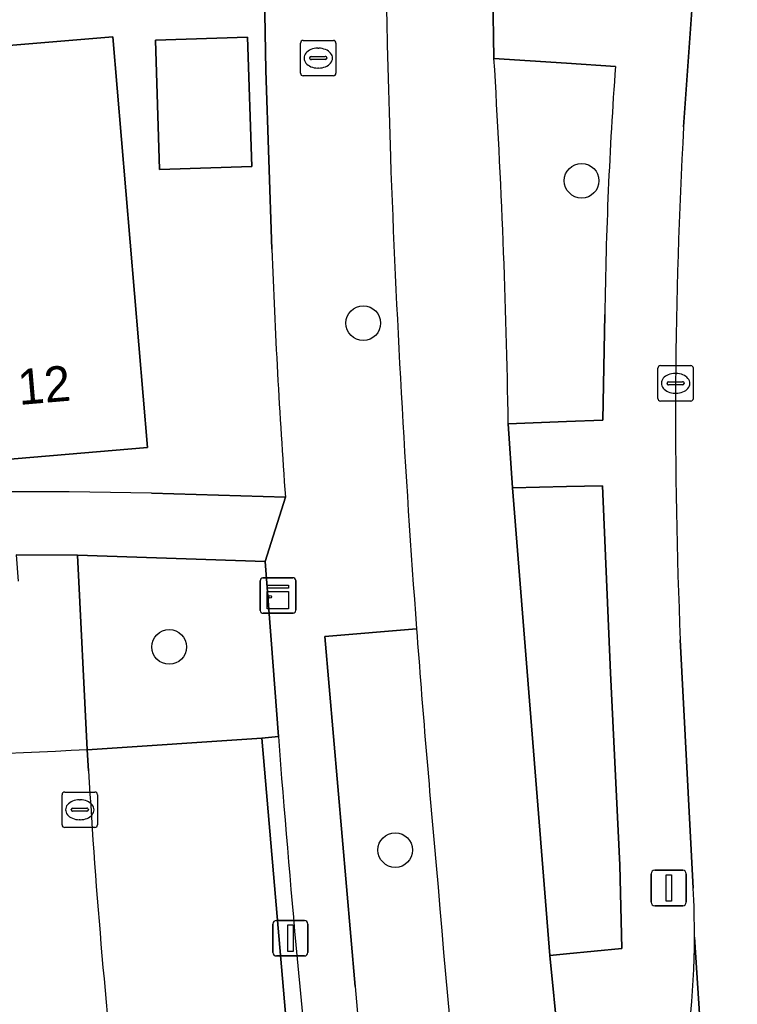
# Model space of a CAD drawing. Extents: x 160157 to 160921, y 381516 to 382045.
# Drawn here: x 160484.57 to 160504.82, y 381640.16 to 381667.92 of the extents above; entities that cross this region are included whole.
import ezdxf

# ---------------------------------------------------------------- set-up
doc = ezdxf.new("R2010")
doc.units = 0
for name, color, linetype in [('IMGEO_Berm_groen', 7, 'Continuous'), ('IMGEO_Boom', 7, 'Continuous'), ('IMGEO_Brandkraan', 7, 'Continuous'), ('IMGEO_Erf', 7, 'Continuous'), ('IMGEO_Fietspad_gesloten', 7, 'Continuous'), ('IMGEO_Groenvoorziening', 7, 'Continuous'), ('IMGEO_Kast', 7, 'Continuous'), ('IMGEO_Kolk', 7, 'Continuous'), ('IMGEO_Lichtmast', 7, 'Continuous'), ('IMGEO_Pand', 7, 'Continuous'), ('IMGEO_Pand_nummerreeks', 7, 'Continuous'), ('IMGEO_Parkeervlak_open', 7, 'Continuous'), ('IMGEO_Rijbaan_lokaal_open', 7, 'Continuous'), ('IMGEO_Rijbaan_regionaal_gesloten', 7, 'Continuous'), ('IMGEO_Verkeerseiland_open', 7, 'Continuous'), ('IMGEO_Voetpad_open', 7, 'Continuous')]:
    doc.layers.add(name, color=color, linetype=linetype)

msp = doc.modelspace()

# ---------------------------------------------------------------- linework, layer by layer
at = {"layer": 'IMGEO_Berm_groen'}
for points in [[(160501.377, 381666.605), (160500, 381666.695), (160497.95, 381666.828)], [(160498.353, 381656.527), (160500, 381656.592), (160501.02, 381656.633), (160501.077, 381659.61)]]:
    msp.add_lwpolyline(points, dxfattribs=at)
msp.add_lwpolyline([(160501.233, 381649.509), (160501.011, 381654.781), (160500, 381654.757), (160498.469, 381654.721), (160499.525, 381641.531), (160500, 381641.577), (160501.557, 381641.728), (160501.502, 381644.083)], close=True, dxfattribs=at)
for centre, radius, start, end in [((160263.469, 381652.496), 234.919, 0.98316, 3.49766), ((160618.795, 381658.065), 117.728, 175.84024, 179.24819)]:
    msp.add_arc(centre, radius, start, end, dxfattribs=at)
at = {"layer": 'IMGEO_Boom'}
for centre in [(160500.423, 381663.382), (160494.263, 381659.367), (160488.788, 381650.234), (160495.165, 381644.507)]:
    msp.add_circle(centre, 0.489, dxfattribs=at)
at = {"layer": 'IMGEO_Brandkraan'}
for p, q in [((160492.491, 381666.413), (160492.491, 381667.265)), ((160492.566, 381667.339), (160493.418, 381667.339)), ((160493.492, 381667.265), (160493.492, 381666.413)), ((160492.979, 381667.119), (160493.004, 381667.119)), ((160492.75, 381666.833), (160492.75, 381666.845)), ((160493.188, 381666.796), (160492.79, 381666.796)), ((160492.793, 381666.882), (160493.191, 381666.882)), ((160493.234, 381666.845), (160493.234, 381666.833)), ((160493.002, 381666.559), (160492.977, 381666.559)), ((160493.418, 381666.339), (160492.566, 381666.339))]:
    msp.add_line(p, q, dxfattribs=at)
for points in [[(160492.491, 381666.413), (160492.491, 381667.265)], [(160492.566, 381667.339), (160493.418, 381667.339)], [(160493.492, 381667.265), (160493.492, 381666.413)], [(160493.418, 381666.339), (160492.566, 381666.339)]]:
    msp.add_lwpolyline(points, dxfattribs=at)
for centre, radius, start, end in [((160492.568, 381667.263), 0.0765, 91.552, 178.448), ((160492.568, 381667.263), 0.0765, 91.552, 178.448), ((160493.416, 381667.263), 0.0765, 1.552, 88.448), ((160493.416, 381667.263), 0.0765, 1.552, 88.448), ((160492.79, 381666.842), 0.0403, 85.8775, 175.7526), ((160492.787, 381666.832), 0.0366, 178.938, 274.7102), ((160493.191, 381666.839), 0.043, 264.8664, 352.4533), ((160493.195, 381666.844), 0.0386, 1.7309, 96.639), ((160492.568, 381666.415), 0.0765, 181.552, 268.448), ((160492.568, 381666.415), 0.0765, 181.552, 268.448), ((160493.416, 381666.415), 0.0765, 271.552, 358.448), ((160493.416, 381666.415), 0.0765, 271.552, 358.448)]:
    msp.add_arc(centre, radius, start, end, dxfattribs=at)
for centre, major_axis, ratio, start_param, end_param in [((160492.978, 381666.839), (-0.387, 0.002), 0.722429, 4.712389, 7.853982), ((160493.003, 381666.839), (-0.39, 0.002), 0.717154, 1.570796, 4.712389)]:
    msp.add_ellipse(centre, major_axis=major_axis, ratio=ratio, start_param=start_param, end_param=end_param, dxfattribs=at)
at = {"layer": 'IMGEO_Erf'}
for points in [[(160491.686, 381661.452), (160491.512, 381666.491), (160491.457, 381669.708), (160491.439, 381672.439), (160491.376, 381681.789), (160491.463, 381687.593), (160491.694, 381694.13), (160492.728, 381711.927)], [(160488.29, 381654.567), (160492.066, 381654.457)]]:
    msp.add_lwpolyline(points, dxfattribs=at)
for points in [[(160461.315, 381665.237), (160466.815, 381665.701), (160466.916, 381664.505), (160471.988, 381664.933), (160472.089, 381663.737), (160476.737, 381664.143), (160476.65, 381665.329), (160481.757, 381665.774), (160481.655, 381666.978), (160487.192, 381667.435), (160488.176, 381655.861), (160482.64, 381655.389), (160477.518, 381654.953), (160472.87, 381654.556), (160467.799, 381654.124), (160462.295, 381653.655)], [(160488.396, 381667.341), (160490.999, 381667.427), (160491.118, 381663.781), (160488.516, 381663.696)]]:
    msp.add_lwpolyline(points, close=True, dxfattribs=at)
for centre, radius, start, end in [((160679.472, 381668.146), 187.905, 182.04142, 184.1776), ((160485.125, 381542.988), 111.624, 88.37544, 97.91678)]:
    msp.add_arc(centre, radius, start, end, dxfattribs=at)
at = {"layer": 'IMGEO_Fietspad_gesloten'}
for points in [[(160497.95, 381666.828), (160497.922, 381668.666)], [(160505.409, 381601.39), (160504.111, 381608.172), (160502.378, 381618.435), (160501.413, 381625.031), (160501.101, 381627.161), (160500, 381636.8), (160499.525, 381641.531), (160498.469, 381654.721), (160498.353, 381656.527)]]:
    msp.add_lwpolyline(points, dxfattribs=at)
for centre, radius, start, end in [((160961.225, 381678.785), 466.43, 179.32125, 181.81004), ((160263.469, 381652.496), 234.919, 0.98316, 3.49766), ((160848.429, 381676.959), 353.637, 182.09162, 184.25039), ((160844.842, 381676.565), 350.03, 184.22954, 185.32615), ((160833.391, 381670.807), 338.126, 184.53487, 187.87102)]:
    msp.add_arc(centre, radius, start, end, dxfattribs=at)
at = {"layer": 'IMGEO_Groenvoorziening'}
msp.add_lwpolyline([(160491.492, 381652.649), (160486.196, 381652.822), (160486.472, 381647.33), (160491.401, 381647.664), (160491.866, 381647.705), (160491.667, 381650.431)], close=True, dxfattribs=at)
for points in [[(160495.765, 381650.749), (160493.18, 381650.533), (160494.031, 381640.656)], [(160491.866, 381647.705), (160491.401, 381647.664), (160492.337, 381636.731), (160487.421, 381636.32), (160487.553, 381635.049), (160492.41, 381635.887)]]:
    msp.add_lwpolyline(points, dxfattribs=at)
for centre, radius, start, end in [((160844.842, 381676.565), 350.03, 184.22954, 185.32615), ((160879.416, 381677.449), 388.689, 184.38877, 188.09689), ((160833.391, 381670.807), 338.126, 184.53487, 187.87102), ((160792.557, 381665.833), 299.586, 184.82081, 190.09257)]:
    msp.add_arc(centre, radius, start, end, dxfattribs=at)
at = {"layer": 'IMGEO_Kast'}
for p, q in [((160491.357, 381651.26), (160491.357, 381652.101)), ((160491.357, 381652.101), (160491.357, 381651.26)), ((160491.432, 381652.185), (160492.273, 381652.185)), ((160492.273, 381652.185), (160491.432, 381652.185)), ((160492.357, 381652.11), (160492.357, 381651.269)), ((160492.357, 381651.269), (160492.357, 381652.11)), ((160492.282, 381651.185), (160491.441, 381651.185)), ((160491.441, 381651.185), (160492.282, 381651.185))]:
    msp.add_line(p, q, dxfattribs=at)
for points in [[(160491.552, 381651.975), (160492.152, 381651.975), (160492.152, 381651.89), (160491.552, 381651.89), (160491.552, 381651.975)], [(160491.552, 381651.8), (160492.152, 381651.8), (160492.152, 381651.311), (160491.552, 381651.311), (160491.552, 381651.8)]]:
    msp.add_lwpolyline(points, dxfattribs=at)
msp.add_circle((160491.636, 381651.649), 0.0377, dxfattribs=at)
for centre, start, end in [((160491.435, 381652.107), 92.4484, 184.2845), ((160491.435, 381652.107), 92.4484, 184.2845), ((160492.279, 381652.107), 2.4484, 94.2845), ((160492.279, 381652.107), 2.4484, 94.2845), ((160491.435, 381651.263), 182.4484, 274.2845), ((160491.435, 381651.263), 182.4484, 274.2845), ((160492.279, 381651.263), 272.4484, 4.2845), ((160492.279, 381651.263), 272.4484, 4.2845)]:
    msp.add_arc(centre, 0.0779, start, end, dxfattribs=at)
at = {"layer": 'IMGEO_Kolk'}
for p, q in [((160502.573, 381657.243), (160502.573, 381658.095)), ((160502.648, 381658.169), (160503.5, 381658.169)), ((160503.574, 381658.095), (160503.574, 381657.243)), ((160503.061, 381657.949), (160503.086, 381657.949)), ((160502.832, 381657.663), (160502.832, 381657.675)), ((160503.27, 381657.626), (160502.872, 381657.626)), ((160502.875, 381657.712), (160503.273, 381657.712)), ((160503.316, 381657.675), (160503.316, 381657.663)), ((160503.084, 381657.389), (160503.059, 381657.389)), ((160503.5, 381657.169), (160502.648, 381657.169)), ((160485.839, 381646.143), (160486.691, 381646.143)), ((160485.764, 381645.217), (160485.764, 381646.069)), ((160486.252, 381645.923), (160486.277, 381645.923)), ((160486.765, 381646.069), (160486.765, 381645.217)), ((160486.023, 381645.637), (160486.023, 381645.649)), ((160486.461, 381645.6), (160486.063, 381645.6)), ((160486.066, 381645.686), (160486.464, 381645.686)), ((160486.507, 381645.649), (160486.507, 381645.637)), ((160486.275, 381645.363), (160486.25, 381645.363)), ((160486.691, 381645.143), (160485.839, 381645.143))]:
    msp.add_line(p, q, dxfattribs=at)
for points in [[(160502.573, 381657.243), (160502.573, 381658.095)], [(160502.648, 381658.169), (160503.5, 381658.169)], [(160503.574, 381658.095), (160503.574, 381657.243)], [(160503.5, 381657.169), (160502.648, 381657.169)], [(160485.839, 381646.143), (160486.691, 381646.143)], [(160485.764, 381645.217), (160485.764, 381646.069)], [(160486.765, 381646.069), (160486.765, 381645.217)], [(160486.691, 381645.143), (160485.839, 381645.143)]]:
    msp.add_lwpolyline(points, dxfattribs=at)
for centre, radius, start, end in [((160502.65, 381658.093), 0.0765, 91.552, 178.448), ((160502.65, 381658.093), 0.0765, 91.552, 178.448), ((160503.498, 381658.093), 0.0765, 1.552, 88.448), ((160503.498, 381658.093), 0.0765, 1.552, 88.448), ((160502.872, 381657.672), 0.0403, 85.8775, 175.7526), ((160502.869, 381657.662), 0.0366, 178.938, 274.7102), ((160503.273, 381657.669), 0.043, 264.8664, 352.4533), ((160503.277, 381657.674), 0.0386, 1.7309, 96.639), ((160502.65, 381657.245), 0.0765, 181.552, 268.448), ((160502.65, 381657.245), 0.0765, 181.552, 268.448), ((160503.498, 381657.245), 0.0765, 271.552, 358.448), ((160503.498, 381657.245), 0.0765, 271.552, 358.448), ((160485.841, 381646.067), 0.0765, 91.552, 178.448), ((160485.841, 381646.067), 0.0765, 91.552, 178.448), ((160486.689, 381646.067), 0.0765, 1.552, 88.448), ((160486.689, 381646.067), 0.0765, 1.552, 88.448), ((160486.063, 381645.646), 0.0403, 85.8775, 175.7526), ((160486.06, 381645.636), 0.0366, 178.938, 274.7102), ((160486.464, 381645.643), 0.043, 264.8664, 352.4533), ((160486.468, 381645.648), 0.0386, 1.7309, 96.639), ((160485.841, 381645.219), 0.0765, 181.552, 268.448), ((160485.841, 381645.219), 0.0765, 181.552, 268.448), ((160486.689, 381645.219), 0.0765, 271.552, 358.448), ((160486.689, 381645.219), 0.0765, 271.552, 358.448)]:
    msp.add_arc(centre, radius, start, end, dxfattribs=at)
for centre, major_axis, ratio, start_param, end_param in [((160503.06, 381657.669), (-0.387, 0.002), 0.722429, 4.712389, 7.853982), ((160503.085, 381657.669), (-0.39, 0.002), 0.717154, 1.570796, 4.712389), ((160486.251, 381645.643), (-0.387, 0.002), 0.722429, 4.712389, 7.853982), ((160486.276, 381645.643), (-0.39, 0.002), 0.717154, 1.570796, 4.712389)]:
    msp.add_ellipse(centre, major_axis=major_axis, ratio=ratio, start_param=start_param, end_param=end_param, dxfattribs=at)
at = {"layer": 'IMGEO_Lichtmast'}
for p, q in [((160502.484, 381643.938), (160503.274, 381643.938)), ((160503.274, 381643.938), (160502.484, 381643.938)), ((160502.384, 381643.038), (160502.384, 381643.838)), ((160502.384, 381643.838), (160502.384, 381643.038)), ((160503.374, 381643.838), (160503.374, 381643.038)), ((160503.374, 381643.038), (160503.374, 381643.838)), ((160503.274, 381642.938), (160502.484, 381642.938)), ((160502.484, 381642.938), (160503.274, 381642.938)), ((160491.811, 381642.521), (160492.601, 381642.521)), ((160492.601, 381642.521), (160491.811, 381642.521)), ((160491.711, 381641.621), (160491.711, 381642.421)), ((160491.711, 381642.421), (160491.711, 381641.621)), ((160492.701, 381642.421), (160492.701, 381641.621)), ((160492.701, 381641.621), (160492.701, 381642.421)), ((160492.601, 381641.521), (160491.811, 381641.521)), ((160491.811, 381641.521), (160492.601, 381641.521))]:
    msp.add_line(p, q, dxfattribs=at)
for points in [[(160502.804, 381643.813), (160502.954, 381643.813), (160502.954, 381643.063), (160502.804, 381643.063), (160502.804, 381643.813)], [(160492.131, 381642.396), (160492.281, 381642.396), (160492.281, 381641.646), (160492.131, 381641.646), (160492.131, 381642.396)]]:
    msp.add_lwpolyline(points, dxfattribs=at)
for centre, start, end in [((160502.484, 381643.838), 90, 180), ((160502.484, 381643.838), 90, 180), ((160503.274, 381643.838), 0, 90), ((160503.274, 381643.838), 360, 90), ((160502.484, 381643.038), 180, 270), ((160502.484, 381643.038), 180, 270), ((160503.274, 381643.038), 270, 0), ((160503.274, 381643.038), 270, 0), ((160491.811, 381642.421), 90, 180), ((160491.811, 381642.421), 90, 180), ((160492.601, 381642.421), 0, 90), ((160492.601, 381642.421), 360, 90), ((160491.811, 381641.621), 180, 270), ((160491.811, 381641.621), 180, 270), ((160492.601, 381641.621), 270, 0), ((160492.601, 381641.621), 270, 0)]:
    msp.add_arc(centre, 0.1, start, end, dxfattribs=at)
at = {"layer": 'IMGEO_Pand'}
for points in [[(160487.192, 381667.435), (160481.655, 381666.978), (160481.757, 381665.774), (160482.64, 381655.389), (160488.176, 381655.861)], [(160488.516, 381663.696), (160491.118, 381663.781), (160490.999, 381667.427), (160488.396, 381667.341)]]:
    msp.add_lwpolyline(points, close=True, dxfattribs=at)
at = {"layer": 'IMGEO_Parkeervlak_open'}
for points in [[(160486.196, 381652.822), (160484.473, 381652.83), (160484.523, 381652.089)], [(160486.472, 381647.33), (160486.196, 381652.822)], [(160487.421, 381636.32), (160492.337, 381636.731), (160491.401, 381647.664), (160486.472, 381647.33)], [(160486.472, 381647.33), (160486.513, 381646.739)]]:
    msp.add_lwpolyline(points, dxfattribs=at)
for centre, radius, start, end in [((160497.989, 381374.552), 273.021, 92.4176, 95.43187), ((160663.736, 381656.935), 177.516, 183.2926, 186.66871)]:
    msp.add_arc(centre, radius, start, end, dxfattribs=at)
at = {"layer": 'IMGEO_Rijbaan_lokaal_open'}
msp.add_lwpolyline([(160486.513, 381646.739), (160486.472, 381647.33)], dxfattribs=at)
for centre, radius, start, end in [((160497.989, 381374.552), 273.021, 92.4176, 95.43187), ((160663.736, 381656.935), 177.516, 183.2926, 186.66871)]:
    msp.add_arc(centre, radius, start, end, dxfattribs=at)
at = {"layer": 'IMGEO_Rijbaan_regionaal_gesloten'}
for points in [[(160503.604, 381669.254), (160503.301, 381664.897)], [(160503.207, 381650.432), (160503.572, 381643.436)], [(160513.263, 381578.224), (160518.288, 381562.954), (160520.942, 381554.801), (160521.023, 381554.575), (160522.336, 381550.885), (160525.665, 381551.463), (160515.13, 381582.184), (160511.982, 381592.095), (160509.289, 381602.139), (160507.057, 381612.296), (160505.607, 381620.479), (160504.911, 381626.12), (160504.346, 381631.776), (160503.912, 381637.443), (160503.606, 381642.054)], [(160503.606, 381642.054), (160503.912, 381637.443), (160504.346, 381631.776), (160504.911, 381626.12), (160505.607, 381620.479), (160507.057, 381612.296), (160509.289, 381602.139), (160511.982, 381592.095), (160515.13, 381582.184)]]:
    msp.add_lwpolyline(points, dxfattribs=at)
for centre, radius, start, end in [((160649.277, 381656.716), 146.205, 176.79214, 182.4632), ((160479.705, 381642.157), 23.901, 359.7521, 3.0665), ((160479.833, 381642.15), 23.773, 348.0499, 359.7677)]:
    msp.add_arc(centre, radius, start, end, dxfattribs=at)
at = {"layer": 'IMGEO_Verkeerseiland_open'}
for points in [[(160503.301, 381664.897), (160503.604, 381669.254), (160501.57, 381669.4), (160501.491, 381668.411), (160500, 381668.518), (160497.922, 381668.666), (160497.95, 381666.828), (160500, 381666.695), (160501.377, 381666.605)], [(160501.077, 381659.61), (160501.02, 381656.633), (160500, 381656.592), (160498.353, 381656.527), (160498.469, 381654.721), (160500, 381654.757), (160501.011, 381654.781), (160501.233, 381649.509), (160501.502, 381644.083), (160501.557, 381641.728), (160500, 381641.577), (160499.525, 381641.531), (160500, 381636.8), (160501.101, 381627.161), (160501.413, 381625.031), (160501.846, 381625.084)], [(160503.572, 381643.436), (160503.207, 381650.432)]]:
    msp.add_lwpolyline(points, dxfattribs=at)
for centre, radius, start, end in [((160618.795, 381658.065), 117.728, 175.84024, 179.24819), ((160649.277, 381656.716), 146.205, 176.79214, 182.4632), ((160479.705, 381642.157), 23.901, 359.7521, 3.0665), ((160479.833, 381642.15), 23.773, 348.0499, 359.7677)]:
    msp.add_arc(centre, radius, start, end, dxfattribs=at)
at = {"layer": 'IMGEO_Voetpad_open'}
for points in [[(160492.728, 381711.927), (160491.694, 381694.13), (160491.463, 381687.593), (160491.376, 381681.789), (160491.439, 381672.439), (160491.457, 381669.708), (160491.512, 381666.491), (160491.686, 381661.452)], [(160484.473, 381652.83), (160486.196, 381652.822), (160491.492, 381652.649), (160492.066, 381654.457), (160488.29, 381654.567)], [(160492.066, 381654.457), (160491.492, 381652.649), (160491.667, 381650.431), (160491.866, 381647.705)], [(160494.031, 381640.656), (160493.18, 381650.533), (160495.765, 381650.749)]]:
    msp.add_lwpolyline(points, dxfattribs=at)
for centre, radius, start, end in [((160961.225, 381678.785), 466.43, 179.32125, 181.81004), ((160848.429, 381676.959), 353.637, 182.09162, 184.25039), ((160679.472, 381668.146), 187.905, 182.04142, 184.1776), ((160485.125, 381542.988), 111.624, 88.37544, 97.91678), ((160879.416, 381677.449), 388.689, 184.38877, 188.09689), ((160792.557, 381665.833), 299.586, 184.82081, 190.09257)]:
    msp.add_arc(centre, radius, start, end, dxfattribs=at)

# ---------------------------------------------------------------- texts
at = {"layer": 'IMGEO_Pand_nummerreeks'}
msp.add_text('12', height=1, rotation=4.8759, dxfattribs=at).set_placement((160484.557, 381657.058))

doc.saveas('drawing.dxf')
